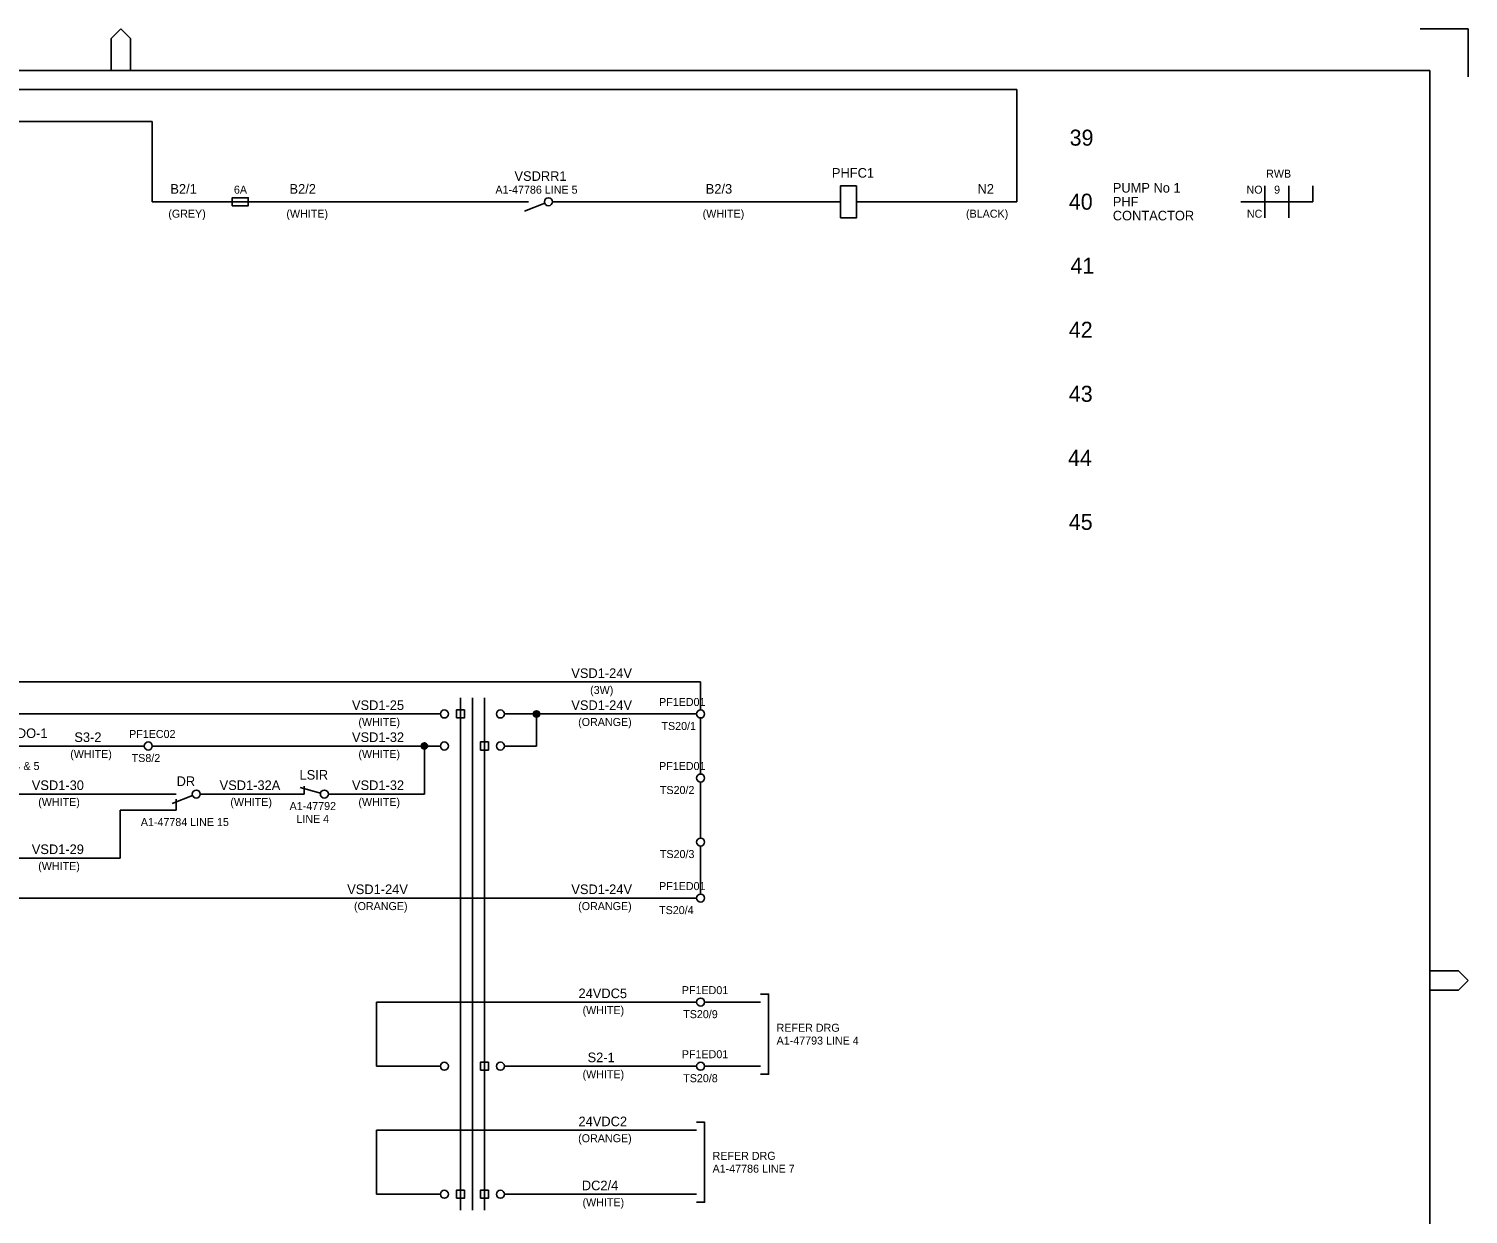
# Model space of a CAD drawing. Extents: x 0 to 841, y 0 to 594.
# Drawn here: x 391.4 to 841, y 223.8 to 594 of the extents above; entities that cross this region are included whole.
import ezdxf

# ---------------------------------------------------------------- set-up
doc = ezdxf.new("R2010")
doc.units = 0
for name, color, linetype in [('A1BORDER', 7, 'Continuous'), ('Level 1', 7, 'Continuous'), ('Level 10', 7, 'Continuous'), ('Level 5', 7, 'Continuous'), ('Level 6', 7, 'Continuous')]:
    doc.layers.add(name, color=color, linetype=linetype)

msp = doc.modelspace()

# ---------------------------------------------------------------- linework, layer by layer
at = {"layer": 'A1BORDER'}
for p, q in [((417.19, 591), (420.19, 594)), ((423.19, 591), (420.19, 594)), ((826, 594), (841, 594)), ((841, 579), (841, 594)), ((417.19, 581), (417.19, 591)), ((423.19, 581), (423.19, 591)), ((28, 581), (829, 581)), ((829, 581), (829, 15)), ((829, 299.76), (838, 299.76)), ((838, 299.76), (841, 296.76)), ((838, 293.76), (841, 296.76)), ((829, 293.76), (838, 293.76))]:
    msp.add_line(p, q, dxfattribs=at)
at = {"layer": 'Level 1'}
for p, q in [((57.5, 575), (700, 575)), ((700, 575), (700, 540)), ((130, 565), (430, 565)), ((430, 565), (430, 540)), ((777.5, 535), (777.5, 545)), ((785, 535), (785, 545)), ((792.5, 540), (792.5, 545)), ((430, 540), (545, 540)), ((547.5, 540), (545, 540)), ((545, 540), (545, 540)), ((555, 540), (555, 540)), ((645, 540), (630, 540)), ((700, 540), (650, 540)), ((770, 540), (792.5, 540)), ((601.25, 381.25), (601.25, 390)), ((526.25, 385), (526.25, 225)), ((530, 385), (530, 225)), ((533.75, 385), (533.75, 225)), ((550, 370), (550, 380)), ((601.25, 361.25), (601.25, 378.75)), ((427.5, 370), (385, 370)), ((515, 370), (515, 355)), ((601.25, 341.25), (601.25, 358.75)), ((477.5, 355), (475, 355)), ((485, 355), (515, 355)), ((435, 350), (420, 350)), ((420, 335), (420, 350)), ((601.25, 323.75), (601.25, 338.75)), ((600, 322.5), (325, 322.5)), ((500, 270), (500, 290)), ((602.5, 290), (620, 290)), ((520, 270), (500, 270)), ((602.5, 270), (620, 270)), ((500, 230), (500, 250)), ((520, 230), (500, 230))]:
    msp.add_line(p, q, dxfattribs=at)
for points in [[(525, 378.75), (527.5, 378.75), (527.5, 381.25), (525, 381.25)], [(532.5, 368.75), (535, 368.75), (535, 371.25), (532.5, 371.25)], [(532.5, 268.75), (535, 268.75), (535, 271.25), (532.5, 271.25)], [(525, 228.75), (527.5, 228.75), (527.5, 231.25), (525, 231.25)], [(532.5, 228.75), (535, 228.75), (535, 231.25), (532.5, 231.25)]]:
    msp.add_lwpolyline(points, close=True, dxfattribs=at)
for points in [[(620, 292.5), (622.5, 292.5), (622.5, 267.5), (620, 267.5)], [(600, 252.5), (602.5, 252.5), (602.5, 227.5), (600, 227.5)]]:
    msp.add_lwpolyline(points, dxfattribs=at)
at = {"layer": 'Level 10'}
for p, q in [((552.59, 539.54), (546.25, 537)), ((549, 380), (549, 380)), ((549.1, 379.56), (549.1, 380.44)), ((549.4, 379.2), (549.4, 380.8)), ((549.7, 379.05), (549.7, 380.95)), ((550, 379), (550, 380.99)), ((550.3, 379.05), (550.3, 380.95)), ((550.6, 379.2), (550.6, 380.8)), ((550.9, 379.56), (550.9, 380.44)), ((514, 370), (514, 370)), ((514.1, 369.56), (514.1, 370.44)), ((514.4, 369.2), (514.4, 370.8)), ((514.7, 369.05), (514.7, 370.95)), ((515, 369), (515, 370.99)), ((515.3, 369.05), (515.3, 370.95)), ((515.6, 369.2), (515.6, 370.8)), ((515.9, 369.56), (515.9, 370.44)), ((482.54, 355.32), (476.25, 357)), ((477.5, 357.5), (477.5, 355)), ((437.5, 355), (435, 355)), ((442.59, 354.54), (436.25, 352)), ((437.5, 353.37), (437.5, 350)), ((437.5, 350), (435, 350))]:
    msp.add_line(p, q, dxfattribs=at)
for points in [[(650, 545), (650, 535), (645, 535), (645, 545), (650, 545)], [(460, 540), (460, 541.25), (455, 541.25), (455, 538.75), (460, 538.75), (460, 540)]]:
    msp.add_lwpolyline(points, dxfattribs=at)
for centre, radius in [((553.75, 540), 1.25), ((550, 380), 1), ((515, 370), 1), ((443.75, 355), 1.25), ((483.75, 355), 1.25)]:
    msp.add_circle(centre, radius, dxfattribs=at)
at = {"layer": 'Level 5'}
for centre in [(521.25, 380), (538.75, 380), (601.25, 380), (428.75, 370), (521.25, 370), (538.75, 370), (601.25, 360), (601.25, 340), (601.25, 322.5), (601.25, 290), (521.25, 270), (538.75, 270), (601.25, 270), (521.25, 230), (538.75, 230)]:
    msp.add_circle(centre, 1.25, dxfattribs=at)
at = {"layer": 'Level 6'}
for p, q in [((555, 540), (645, 540)), ((142.5, 390), (601.25, 390)), ((260, 380), (520, 380)), ((540, 380), (600, 380)), ((430, 370), (520, 370)), ((540, 370), (550, 370)), ((325, 355), (435, 355)), ((445, 355), (475, 355)), ((365, 335), (420, 335)), ((500, 290), (600, 290)), ((540, 270), (600, 270)), ((500, 250), (600, 250)), ((540, 230), (600, 230))]:
    msp.add_line(p, q, dxfattribs=at)

# ---------------------------------------------------------------- texts
at = {"layer": 'Level 1'}
for s, height, p in [('39', 5, (716.52, 557.5)), ('RWB', 2.5, (777.89, 547.5)), ('NO', 2.5, (771.76, 542.5)), ('9', 2.5, (780.38, 542.5)), ('40', 5, (716.27, 537.5)), ('NC', 2.5, (771.88, 535)), ('41', 5, (716.77, 517.5)), ('42', 5, (716.27, 497.5)), ('43', 5, (716.27, 477.5)), ('44', 5, (716.02, 457.5)), ('45', 5, (716.27, 437.5)), ('PF1ED01', 2.5, (588.29, 382.5)), ('PF1EC02', 2.5, (422.77, 372.5)), ('PF1ED01', 2.5, (588.29, 362.5)), ('PF1ED01', 2.5, (588.29, 325)), ('PF1ED01', 2.5, (595.4, 292.5)), ('REFER DRG', 2.5, (625, 280.75)), ('A1-47793 LINE 4', 2.5, (625, 276.75)), ('PF1ED01', 2.5, (595.4, 272.5)), ('REFER DRG', 2.5, (605, 240.75)), ('A1-47786 LINE 7', 2.5, (605, 236.75))]:
    msp.add_text(s, height=height, dxfattribs=at).set_placement(p)
at = {"layer": 'Level 5'}
for s, height, p in [('VSDRR1', 3, (543.13, 546.5)), ('PHFC1', 3, (642.27, 547.5)), ('B2/1', 3, (435.67, 542.5)), ('6A', 2.5, (455.51, 542.5)), ('B2/2', 3, (472.87, 542.5)), ('A1-47786 LINE 5', 2.5, (537.18, 542.5)), ('B2/3', 3, (602.87, 542.5)), ('N2', 3, (687.76, 542.5)), ('PUMP No 1', 3, (730, 542.84)), ('PHF', 3, (730, 538.5)), ('(GREY)', 2.5, (435.02, 535)), ('(WHITE)', 2.5, (471.9, 535)), ('(WHITE)', 2.5, (601.9, 535)), ('(BLACK)', 2.5, (684.15, 535)), ('CONTACTOR', 3, (730, 534.16)), ('VSD1-24V', 3, (560.88, 391.25)), ('(3W)', 2.5, (566.76, 386.25)), ('VSD1-25', 3, (492.38, 381.25)), ('VSD1-24V', 3, (560.89, 381.25)), ('(WHITE)', 2.5, (494.39, 376.25)), ('(ORANGE)', 2.5, (563.02, 376.25)), ('TS20/1', 2.5, (589.04, 375)), ('RTU SLOT 3 DO-1', 3, (363.42, 372.5)), ('S3-2', 3, (405.67, 371.25)), ('VSD1-32', 3, (492.38, 371.25)), ('(WHITE)', 2.5, (404.39, 366.25)), ('(WHITE)', 2.5, (494.39, 366.25)), ('A1-47794 LINE 4 & 5', 2.5, (363.19, 362.5)), ('TS8/2', 2.5, (423.58, 365)), ('DR', 3, (437.61, 357.5)), ('LSIR', 3, (476.01, 359.5)), ('VSD1-30', 3, (392.38, 356.25)), ('VSD1-32A', 3, (451.04, 356.25)), ('VSD1-32', 3, (492.38, 356.25)), ('TS20/2', 2.5, (588.55, 355)), ('(WHITE)', 2.5, (394.39, 351.25)), ('(WHITE)', 2.5, (454.39, 351.25)), ('A1-47792', 2.5, (472.9, 350)), ('(WHITE)', 2.5, (494.39, 351.25)), ('A1-47784 LINE 15', 2.5, (426.43, 345)), ('LINE 4', 2.5, (475.02, 346)), ('VSD1-29', 3, (392.38, 336.25)), ('TS20/3', 2.5, (588.55, 335)), ('(WHITE)', 2.5, (394.39, 331.25)), ('VSD1-24V', 3, (490.89, 323.75)), ('VSD1-24V', 3, (560.89, 323.75)), ('(ORANGE)', 2.5, (493.02, 318.75)), ('(ORANGE)', 2.5, (563.02, 318.75)), ('TS20/4', 2.5, (588.3, 317.5)), ('24VDC5', 3, (563.13, 291.25)), ('(WHITE)', 2.5, (564.39, 286.25)), ('TS20/9', 2.5, (595.83, 285)), ('S2-1', 3, (565.97, 271.25)), ('(WHITE)', 2.5, (564.39, 266.25)), ('TS20/8', 2.5, (595.83, 265)), ('24VDC2', 3, (563.13, 251.25)), ('(ORANGE)', 2.5, (563.02, 246.25)), ('DC2/4', 3, (564.17, 231.25)), ('(WHITE)', 2.5, (564.39, 226.25))]:
    msp.add_text(s, height=height, dxfattribs=at).set_placement(p)

doc.saveas('drawing.dxf')
